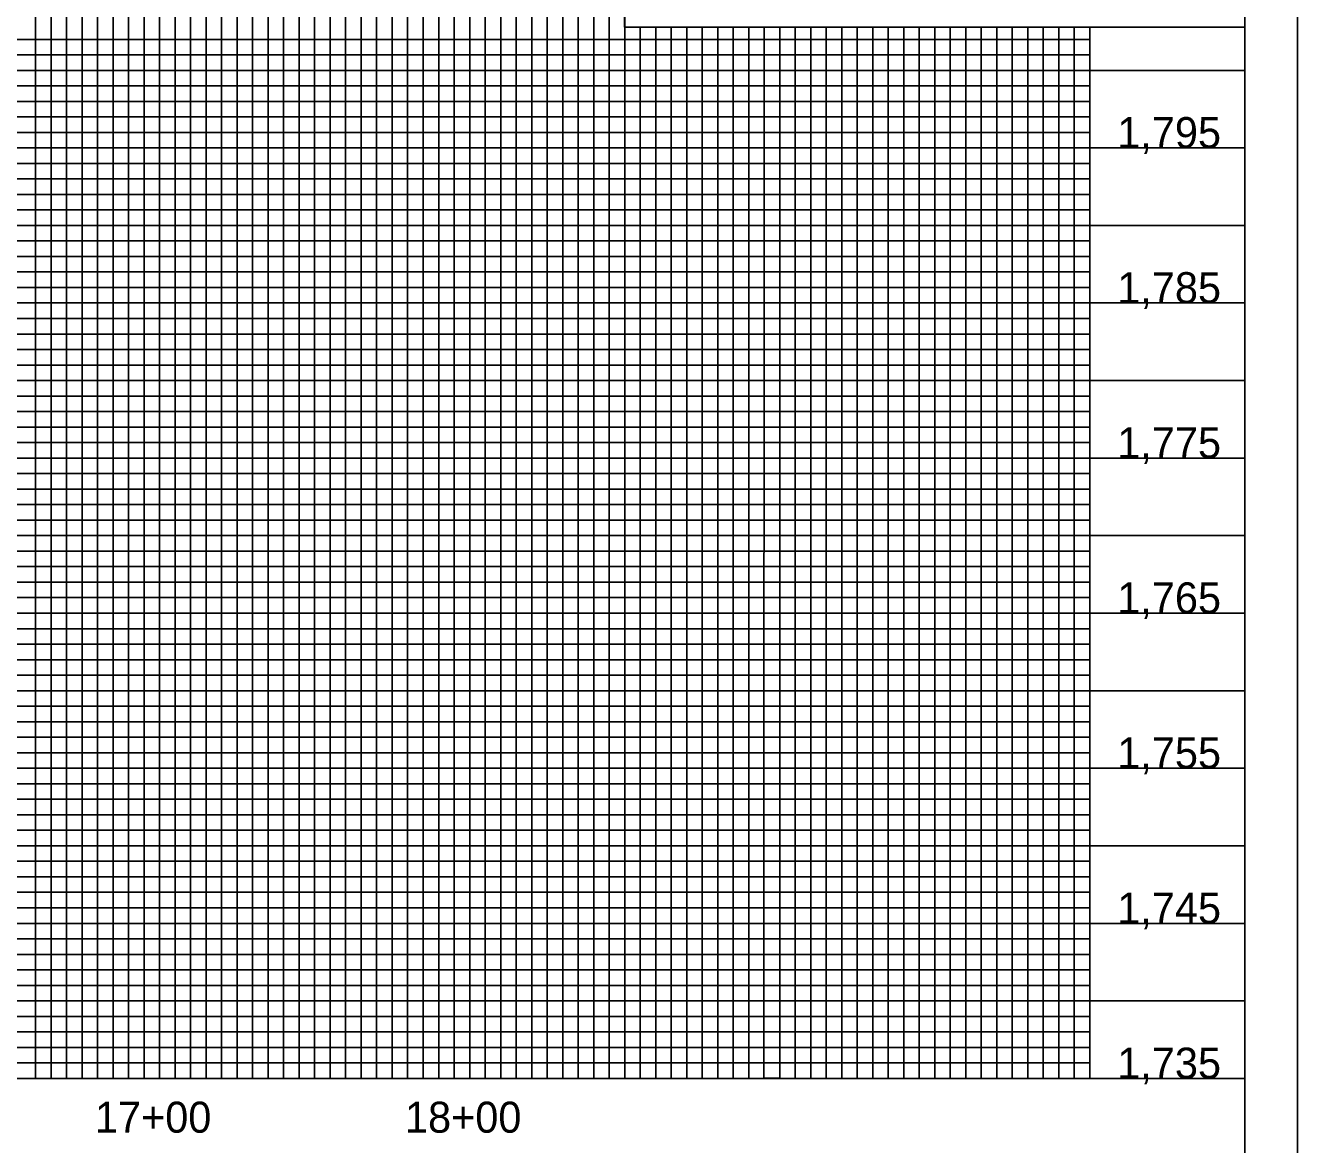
# Model space of a CAD drawing. Extents: x 505602 to 507286, y 483109 to 489436.
# Drawn here: x 506875.8 to 507286.1, y 483662.4 to 484023.2 of the extents above; entities that cross this region are included whole.
import ezdxf

# ---------------------------------------------------------------- set-up
doc = ezdxf.new("R2010")
doc.units = 0
for name, color, linetype in [('Exist Vertical Profile Vertical Axis Label', 7, 'Continuous'), ('Sheet Layout Profile Border Port 1', 7, 'Continuous'), ('Sheet Plot Border Outside CELL', 7, 'Continuous'), ('Sheet Profile CELL', 7, 'Continuous'), ('Sheet Profile Grid Major CELL', 7, 'Continuous'), ('Sheet Profile Grid Middle CELL', 7, 'Continuous'), ('Sheet Profile Grid Minor CELL', 7, 'Continuous'), ('Sheet Sticker Exception Certification CELL', 7, 'Continuous')]:
    doc.layers.add(name, color=color, linetype=linetype)

msp = doc.modelspace()

# ---------------------------------------------------------------- linework, layer by layer
at = {"layer": 'Sheet Layout Profile Border Port 1'}
msp.add_lwpolyline([(506119.08, 484183.71), (507069.08, 484183.71), (507069.08, 483683.71), (506119.08, 483683.71)], close=True, dxfattribs=at)
at = {"layer": 'Sheet Plot Border Outside CELL'}
msp.add_lwpolyline([(505602.08, 483108.71), (507286.08, 483108.71), (507286.08, 484208.71), (505602.08, 484208.71)], close=True, dxfattribs=at)
at = {"layer": 'Sheet Profile CELL'}
msp.add_line((505769.08, 483683.71), (507269.08, 483683.71), dxfattribs=at)
msp.add_lwpolyline([(507269.08, 484183.71), (505769.08, 484183.71), (505769.08, 483133.71), (507269.08, 483133.71)], close=True, dxfattribs=at)
at = {"layer": 'Sheet Profile Grid Major CELL'}
for points in [[(506869.08, 484183.71), (506919.08, 484183.71), (506919.08, 483683.71), (506969.08, 483683.71), (506969.08, 484183.71), (507019.08, 484183.71), (507019.08, 483683.71), (507069.08, 483683.71), (507069.08, 484183.71), (507095.38, 484183.71)], [(507219.08, 484022.66), (507219.08, 483683.71), (507269.08, 483683.71), (507269.08, 484033.71)], [(507119.08, 484022.66), (507119.08, 483683.71), (507169.08, 483683.71), (507169.08, 483683.71), (507169.08, 484022.66)], [(507269.08, 483983.71), (505769.08, 483983.71), (505769.08, 483933.71), (507269.08, 483933.71)], [(507269.08, 483883.71), (505769.08, 483883.71), (505769.08, 483833.71), (507269.08, 483833.71)], [(507269.08, 483783.71), (505769.08, 483783.71), (505769.08, 483783.71), (505769.08, 483733.71), (507269.08, 483733.71)]]:
    msp.add_lwpolyline(points, dxfattribs=at)
at = {"layer": 'Sheet Profile Grid Middle CELL'}
for points in [[(506844.08, 483683.71), (506894.08, 483683.71), (506894.08, 484183.71), (506944.08, 484183.71), (506944.08, 483683.71), (506994.08, 483683.71), (506994.08, 484183.71), (507044.08, 484183.71), (507044.08, 483683.71), (507094.08, 483683.71), (507094.08, 484022.66)], [(507094.08, 483946.51), (507094.08, 483683.71), (507144.08, 483683.71), (507144.08, 484022.66)], [(507144.08, 483946.51), (507144.08, 483683.71), (507194.08, 483683.71), (507194.08, 484022.66)], [(507269.08, 484008.71), (505769.08, 484008.71), (505769.08, 483958.71), (507094.08, 483958.71)], [(507094.08, 483958.71), (507269.08, 483958.71)], [(507269.08, 483908.71), (505769.08, 483908.71), (505769.08, 483858.71), (507269.08, 483858.71)], [(507269.08, 483808.71), (505769.08, 483808.71), (505769.08, 483758.71), (507269.08, 483758.71)], [(507269.08, 483708.71), (505769.08, 483708.71)]]:
    msp.add_lwpolyline(points, dxfattribs=at)
at = {"layer": 'Sheet Profile Grid Minor CELL'}
for p, q in [((505819.08, 484018.71), (507219.08, 484018.71)), ((507219.08, 483998.71), (505819.08, 483998.71)), ((505819.08, 483993.71), (507219.08, 483993.71)), ((507219.08, 483973.71), (505819.08, 483973.71)), ((505819.08, 483968.71), (507219.08, 483968.71)), ((507219.08, 483948.71), (505819.08, 483948.71)), ((505819.08, 483943.71), (507219.08, 483943.71)), ((507219.08, 483938.71), (505819.08, 483938.71)), ((505819.08, 483928.71), (507219.08, 483928.71)), ((507219.08, 483923.71), (505819.08, 483923.71)), ((505819.08, 483918.71), (507219.08, 483918.71)), ((507219.08, 483913.71), (505819.08, 483913.71)), ((505819.08, 483903.71), (507219.08, 483903.71)), ((507219.08, 483898.71), (505819.08, 483898.71)), ((505819.08, 483893.71), (507219.08, 483893.71)), ((507219.08, 483888.71), (505819.08, 483888.71)), ((505819.08, 483878.71), (507219.08, 483878.71)), ((507219.08, 483873.71), (505819.08, 483873.71)), ((505819.08, 483868.71), (507219.08, 483868.71)), ((507219.08, 483863.71), (505819.08, 483863.71)), ((505819.08, 483853.71), (507219.08, 483853.71)), ((507219.08, 483848.71), (505819.08, 483848.71)), ((505819.08, 483843.71), (507219.08, 483843.71)), ((507219.08, 483838.71), (505819.08, 483838.71)), ((505819.08, 483828.71), (507219.08, 483828.71)), ((507219.08, 483823.71), (505819.08, 483823.71)), ((505819.08, 483818.71), (507219.08, 483818.71)), ((507219.08, 483813.71), (505819.08, 483813.71)), ((505819.08, 483803.71), (507219.08, 483803.71)), ((507219.08, 483798.71), (505819.08, 483798.71)), ((507219.08, 483793.71), (505819.08, 483793.71)), ((507219.08, 483788.71), (505819.08, 483788.71)), ((505819.08, 483778.71), (507219.08, 483778.71)), ((507219.08, 483773.71), (505819.08, 483773.71)), ((505819.08, 483768.71), (507219.08, 483768.71)), ((507219.08, 483763.71), (505819.08, 483763.71)), ((505819.08, 483753.71), (507219.08, 483753.71)), ((507219.08, 483748.71), (505819.08, 483748.71)), ((505819.08, 483743.71), (507219.08, 483743.71)), ((507219.08, 483738.71), (505819.08, 483738.71)), ((505819.08, 483728.71), (507219.08, 483728.71)), ((507219.08, 483723.71), (505819.08, 483723.71)), ((505819.08, 483718.71), (507219.08, 483718.71)), ((507219.08, 483713.71), (505819.08, 483713.71)), ((505819.08, 483703.71), (507219.08, 483703.71)), ((507219.08, 483698.71), (505819.08, 483698.71)), ((505819.08, 483693.71), (507219.08, 483693.71))]:
    msp.add_line(p, q, dxfattribs=at)
for points in [[(506874.08, 483683.71), (506879.08, 483683.71), (506879.08, 484183.71)], [(506884.08, 484183.71), (506884.08, 483683.71), (506889.08, 483683.71), (506889.08, 484183.71)], [(506899.08, 484183.71), (506899.08, 483683.71), (506904.08, 483683.71), (506904.08, 484183.71)], [(506909.08, 484183.71), (506909.08, 483683.71), (506914.08, 483683.71), (506914.08, 484183.71)], [(506924.08, 484183.71), (506924.08, 483683.71), (506929.08, 483683.71), (506929.08, 484183.71)], [(506934.08, 484183.71), (506934.08, 483683.71), (506939.08, 483683.71), (506939.08, 484183.71)], [(506949.08, 484183.71), (506949.08, 483683.71), (506954.08, 483683.71), (506954.08, 484183.71)], [(506959.08, 484183.71), (506959.08, 483683.71)], [(506959.08, 483683.71), (506964.08, 483683.71), (506964.08, 484183.71)], [(506974.08, 484183.71), (506974.08, 483683.71), (506979.08, 483683.71), (506979.08, 484183.71)], [(506984.08, 484183.71), (506984.08, 483683.71), (506989.08, 483683.71), (506989.08, 484183.71)], [(506999.08, 484183.71), (506999.08, 483683.71), (507004.08, 483683.71), (507004.08, 484183.71)], [(507009.08, 484183.71), (507009.08, 483683.71), (507014.08, 483683.71), (507014.08, 484183.71)], [(507024.08, 484183.71), (507024.08, 483683.71), (507029.08, 483683.71), (507029.08, 484183.71)], [(507034.08, 484183.71), (507034.08, 483683.71), (507039.08, 483683.71), (507039.08, 484183.71)], [(507049.08, 484183.71), (507049.08, 483683.71), (507054.08, 483683.71), (507054.08, 484183.71)], [(507059.08, 484183.71), (507059.08, 483683.71), (507064.08, 483683.71), (507064.08, 484183.71)], [(507074.08, 484022.66), (507074.08, 483683.71), (507079.08, 483683.71), (507079.08, 484022.66)], [(507084.08, 484022.66), (507084.08, 483683.71), (507089.08, 483683.71), (507089.08, 484022.66)], [(507099.08, 484022.66), (507099.08, 483683.71), (507099.08, 483683.71), (507104.08, 483683.71), (507109.08, 483683.71), (507109.08, 484022.66)], [(507104.08, 484022.66), (507104.08, 483683.71)], [(507114.07, 484022.66), (507113.98, 483683.76), (507118.98, 483683.76), (507124.08, 483683.71), (507124.08, 484022.66)], [(507124.08, 483946.51), (507124.08, 483683.71), (507129.08, 483683.71), (507129.08, 484022.66)], [(507134.08, 484022.66), (507134.08, 483683.71), (507139.08, 483683.71), (507139.08, 484022.66)], [(507149.08, 484022.66), (507149.08, 483683.71), (507154.08, 483683.71), (507154.08, 484022.66)], [(507159.08, 484022.66), (507159.08, 483683.71), (507164.08, 483683.71), (507164.08, 484022.66)], [(507174.08, 484022.66), (507174.08, 483683.71), (507179.08, 483683.71), (507179.08, 484022.66)], [(507184.08, 484022.66), (507184.08, 483683.71), (507189.08, 483683.71), (507189.08, 484022.66)], [(507199.08, 484022.66), (507199.08, 483683.71), (507204.08, 483683.71), (507204.08, 484022.66)], [(507209.08, 484022.66), (507209.08, 483683.71), (507214.08, 483683.71), (507214.08, 484022.66)], [(507219.08, 484013.71), (505819.08, 484013.71), (505819.08, 484003.71), (507219.08, 484003.71)], [(507219.08, 483988.71), (505819.08, 483988.71), (505819.08, 483978.71), (507219.08, 483978.71)], [(507219.08, 483963.71), (505819.08, 483963.71), (505819.08, 483953.71), (507219.08, 483953.71)], [(507219.08, 483688.71), (505819.08, 483688.71)]]:
    msp.add_lwpolyline(points, dxfattribs=at)
at = {"layer": 'Sheet Sticker Exception Certification CELL'}
for p, q in [((507069.03, 484022.66), (507069.03, 484046.16)), ((507069.03, 484022.66), (507069.03, 484046.16)), ((507269.07, 484046.15), (507269.07, 484022.65)), ((507269.07, 484046.15), (507269.07, 484022.65)), ((507269.07, 484022.66), (507069.03, 484022.66)), ((507269.07, 484022.66), (507069.03, 484022.66))]:
    msp.add_line(p, q, dxfattribs=at)

# ---------------------------------------------------------------- texts
at = {"layer": 'Exist Vertical Profile Vertical Axis Label'}
for s, p in [('1,795', (507227.93, 483983.64)), ('1,785', (507227.93, 483933.64)), ('1,775', (507227.93, 483883.64)), ('1,765', (507227.93, 483833.64)), ('1,755', (507227.93, 483783.64)), ('1,745', (507227.93, 483733.64)), ('1,735', (507227.93, 483683.64)), ('17+00', (506898.21, 483666.21)), ('18+00', (506998.21, 483666.21))]:
    msp.add_text(s, height=10, dxfattribs=at).set_placement(p)

doc.saveas('drawing.dxf')
